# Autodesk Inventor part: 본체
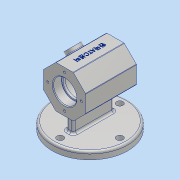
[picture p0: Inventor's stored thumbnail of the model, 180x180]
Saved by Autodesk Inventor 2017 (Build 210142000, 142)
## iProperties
Part Number: 본체
Material: 알루미늄 6061
Document SubType Name: Modeling
Designer: 222
Density: 2.7 g/cm^3
Appearance: 알루미늄 - 평지
Mass: 556.75 g
Surface Area: 509.677 cm^2
Volume: 206.204 cm^3
Author: 222
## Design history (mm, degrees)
sketch "스케치1"
  geometry: L1 (-12.012, 29)-(12.012, 29); L2 (12.012, 29)-(29, 12.012); L3 (29, 12.012)-(29, -12.012); L4 (29, -12.012)-(12.012, -29); L5 (12.012, -29)-(-12.012, -29); L6 (-12.012, -29)-(-29, -12.012); L7 (-29, -12.012)-(-29, 12.012); L8 (-29, 12.012)-(-12.012, 29); C1 r 29 at (0, 0); 2 further points
  constraints: 16 end point, 2 coincident, 1 centre point, 1 horizontal, 1 tangent, 17 other
  dimensions: "d0" = 58 diameter of C1
extrude "돌출1" new body sketch "스케치1" stored distance "d1" = 70; taper "d2" = 0 deg
sketch "스케치3"
  geometry: L1 (-35, 12.012)-(-35, -12.012) reference; L2 (35, -12.012)-(35, 12.012) reference; L3 (-23, 0)-(-23, 16); L4 (-23, 16)-(-35, 16); L5 (-35, 16)-(-35, 0); L6 (-20, 0)-(-20, 14); L7 (-20, 14)-(-23, 14); L8 (-23, 14)-(-23, 0); L9 (20, 0)-(20, 22); L10 (20, 22)-(-20, 22); L11 (-20, 22)-(-20, 0); L12 (23, 0)-(23, 14); L13 (23, 14)-(20, 14); L14 (20, 14)-(20, 0); L15 (35, 0)-(35, 16); L16 (35, 16)-(23, 16); L17 (23, 16)-(23, 0); 1 further point
  constraints: 30 end point, 5 collinear, 5 horizontal, 5 horizontal alignment, 5 parallel, 5 vertical, 1 midpoint, 10 other
  dimensions: "d9" = 28 dimension on L13; "d10" = 32 dimension on L16; "d11" = 12 distance between parallel lines of L2 L12; "d12" = 40 distance between parallel lines of L9 L11; "d13" = 44 dimension on L10
revolve "회전1" sketch "스케치3" stored, may be unused: angle "d14" = 90 deg
fillet "모깎기1" dims "d15" = 3
node "작업 평면1"
sketch "스케치4"
  geometry: C1 r 52 at (0, 0); 1 further point
  constraints: 1 centre point, 1 coincident
  dimensions: "d17" = 104 diameter of C1
extrude "돌출2" join sketch "스케치4" distance "d18" = 10; taper "d19" = 0 deg
fillet "모깎기2" dims "d20" = 3
sketch "스케치5" dims "d21" = 82
  geometry: 3 further points
  constraints: 2 horizontal alignment, 1 coincident, 2 other
hole "구멍1" sketch "스케치5" at (41, 0) diameter "d22" = 9; stored, may be unused: countersink angle "d26" = 90 deg, drill point angle "d28" = 118 deg; dims "d23" = 6, "d24" = 4, "d25" = 2, "d27" = 8
sketch "스케치6"
  geometry: L1 (5, -28)-(-5, -28); L2 (-5, -28)-(-5, 28); L3 (-5, 28)-(5, 28); L4 (5, 28)-(5, -28); L5 (5, -28)-(-5, 28); L6 (-5, -28)-(5, 28); 1 further point
  constraints: 12 end point, 2 midpoint, 2 parallel, 1 horizontal, 1 perpendicular
  dimensions: "d32" = 56 distance of L1.end L2.end; "d33" = 10 distance between parallel lines of L2 L4
extrude "돌출3" join sketch "스케치6" stored distance "d34" = 10; taper "d35" = 0 deg
sketch "스케치7" dims "d36" = 46
  geometry: 3 further points
  constraints: 2 vertical alignment, 1 coincident, 2 other
hole "구멍2" sketch "스케치7" at (0, 23) diameter "d37" = 3.242; stored, may be unused: countersink angle "d41" = 90 deg, drill point angle "d43" = 118 deg; dims "d38" = 8, "d39" = 4, "d40" = 2, "d42" = 10
fillet "모깎기3" dims "d47" = 0.3
fillet "모깎기4" dims "d49" = 1
sketch "스케치9"
  geometry: L1 (-36.5, -62)-(-36.5, -52) reference; L2 (-36.5, -52)-(-5, -52) reference; L3 (-5, -52)-(-5, -29) reference; L4 (-5, -29)-(-11.598, -29) reference; L5 (-12.305, -28.707)-(-28.707, -12.305) reference; L6 (-29, -11.598)-(-29, 11.598) reference; L7 (-28.707, 12.305)-(-12.305, 28.707) reference; L8 (-11.598, 29)-(11.598, 29) reference; L9 (12.305, 28.707)-(28.707, 12.305) reference; L10 (29, 11.598)-(29, -11.598) reference; L11 (28.707, -12.305)-(12.305, -28.707) reference; L12 (11.598, -29)-(5, -29) reference; L13 (5, -29)-(5, -52) reference; L14 (5, -52)-(36.5, -52) reference; L15 (36.5, -52)-(36.5, -62) reference; L16 (36.5, -62)-(-36.5, -62) reference; L17 (52, -55)-(52, -62) reference; L18 (52, -62)-(45.5, -62) reference; L19 (45.5, -62)-(45.5, -52) reference; L20 (45.5, -52)-(49, -52) reference; L21 (-49, -52)-(-45.5, -52) reference; L22 (-45.5, -52)-(-45.5, -62) reference; L23 (-45.5, -62)-(-52, -62) reference; L24 (-52, -62)-(-52, -55) reference; L25 (24.042, 24.042)-(0, 0); L26 (0, 0)-(44.261, 0); L27 (31.113, 16.971)-(27.577, 13.435); L28 (27.577, 13.435)-(20.506, 20.506); L29 (20.506, 20.506)-(24.042, 24.042); L30 (24.042, 24.042)-(31.113, 16.971); C1 r 22 at (0, 0) reference; A1 r 1 centre (-11.598, -28) between (-12.305, -28.707) and (-11.598, -29) reference; A2 r 1 centre (-28, -11.598) between (-29, -11.598) and (-28.707, -12.305) reference; A3 r 1 centre (-28, 11.598) between (-28.707, 12.305) and (-29, 11.598) reference; A4 r 1 centre (-11.598, 28) between (-11.598, 29) and (-12.305, 28.707) reference; A5 r 1 centre (11.598, 28) between (12.305, 28.707) and (11.598, 29) reference; A6 r 1 centre (28, 11.598) between (29, 11.598) and (28.707, 12.305) reference; A7 r 1 centre (28, -11.598) between (28.707, -12.305) and (29, -11.598) reference; A8 r 1 centre (11.598, -28) between (11.598, -29) and (12.305, -28.707) reference; A9 r 3 centre (49, -55) between (52, -55) and (49, -52) reference; A10 r 3 centre (-49, -55) between (-49, -52) and (-52, -55) reference; 1 further point
  constraints: 12 end point, 2 collinear, 2 parallel, 1 horizontal, 1 perpendicular
  dimensions: "d50" = 45 deg angle of L26 L25; "d51" = 20 diameter of L27 L29; "d52" = 5 distance between parallel lines of L9 L30
revolve "회전2" sketch "스케치9" stored, may be unused: angle "d53" = 90 deg
sketch "스케치10"
  geometry: 2 further points
  constraints: 1 coincident
hole "구멍3" sketch "스케치10" at (0, 0) diameter "d54" = 16; stored, may be unused: countersink angle "d58" = 90 deg, drill point angle "d60" = 0 deg; dims "d55" = 8, "d56" = 16, "d57" = 2, "d59" = 2
sketch "스케치11"
  geometry: C1 r 8 at (0, 0) reference; 2 further points
  constraints: 1 coincident
hole "구멍4" sketch "스케치11" at (0, 0) diameter "d61" = 10.917; stored, may be unused: countersink angle "d65" = 90 deg, drill point angle "d67" = 0 deg; dims "d62" = 30, "d63" = 16, "d64" = 2, "d66" = 30
fillet "모깎기5" dims "d68" = 1
chamfer "모따기1" distance "d69" = 1; stored, may be unused: second distance "d70" = 2, angle "d71" = 45 deg
sketch "스케치12"
  geometry: L1 (0, 70)-(23.196, 70) reference; L2 (-17.402, 70)-(-17.402, 0) reference; L3 (40.305, 70)-(40.305, 0) reference; L4 (23.903, 70)-(40.305, 70) reference; 2 further points
  constraints: 1 other
  dimensions: "d81" = 29 distance from line of point (11.305, 35) L3; "d82" = 35 distance from line of point (11.305, 35) L4
feature "엠보싱1" sketch "스케치12" dims "d0" = 58, "d9" = 28, "d10" = 32, "d11" = 12, "d12" = 40, "d13" = 44, "d74" = 0.5, "d75" = 0
fillet "모깎기6" dims "d76" = 3
fillet "모깎기7" dims "d77" = 3
chamfer "모따기2" distance "d78" = 1; stored, may be unused: second distance "d79" = 2, angle "d80" = 45 deg
node "솔리드1"
pattern_circular "원형 패턴1" dims angle "d30" = 360 deg
pattern_circular "원형 패턴2" dims angle "d45" = 360 deg
mirror "미러1"
node "절단 모서리 투영5"
other parameters: "d16" = -62
